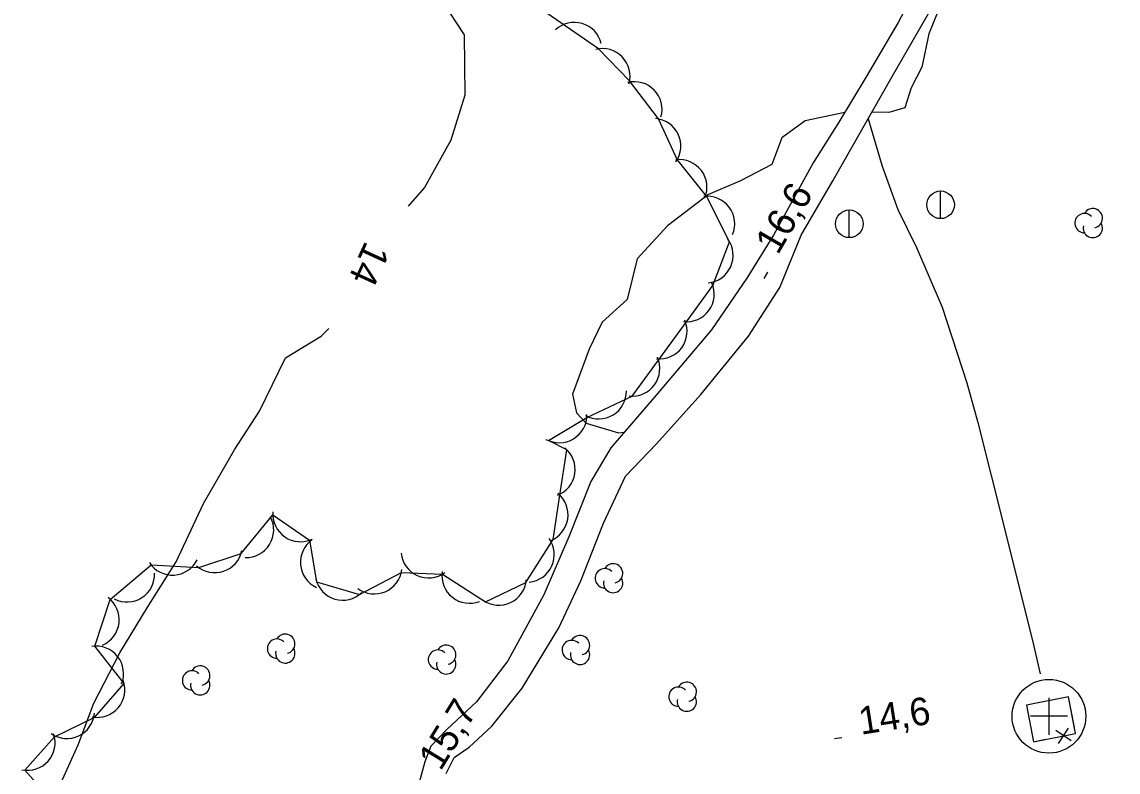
# Model space of a CAD drawing. Extents: x 643342 to 646936, y 5873857 to 5876103.
# Drawn here: x 645870.1 to 645989.1, y 5875433.1 to 5875514.5 of the extents above; entities that cross this region are included whole.
import ezdxf

# ---------------------------------------------------------------- set-up
doc = ezdxf.new("R2010")
doc.units = 0
for name, color, linetype in [('Niveau 2', 7, 'Continuous'), ('Niveau 21', 7, 'Continuous'), ('Niveau 22', 7, 'Continuous'), ('Niveau 3', 7, 'Continuous'), ('Niveau 34', 7, 'Continuous'), ('Niveau 36', 7, 'Continuous'), ('Niveau 37', 7, 'Continuous'), ('Niveau 44', 7, 'Continuous')]:
    doc.layers.add(name, color=color, linetype=linetype)

msp = doc.modelspace()

# ---------------------------------------------------------------- linework, layer by layer
at = {"layer": 'Niveau 2'}
for points in [[(645972.21, 5875521.47), (645972.26, 5875521.25), (645970.38, 5875517.91), (645968.52, 5875513.24), (645967.77, 5875509.63), (645966.59, 5875507.36), (645965.89, 5875505.2), (645964.16, 5875504.69), (645962.33, 5875504.72)], [(645912.02, 5875494.55), (645913.77, 5875496.53), (645916.66, 5875501.73), (645918.18, 5875506.6), (645918.11, 5875513.13), (645915.77, 5875516.71)], [(645959.38, 5875504.71), (645955.1, 5875503.81), (645952.55, 5875501.95), (645951.46, 5875499.07), (645948.07, 5875497.3), (645944.6, 5875495.81), (645940.16, 5875492.4), (645936.86, 5875488.81), (645935.76, 5875484.4), (645933.04, 5875481.93), (645931.66, 5875479.02), (645929.85, 5875474.12), (645930.25, 5875472.1), (645931.32, 5875470.98), (645934.84, 5875469.94), (645935.45, 5875470)], [(645874.15, 5875431.58), (645876.18, 5875436.1), (645877.87, 5875440.59), (645880.68, 5875446.08), (645883.67, 5875450.94), (645886.83, 5875455.94), (645889.78, 5875462.27), (645893.19, 5875468.17), (645895.86, 5875472.29), (645898.69, 5875478.07), (645902.55, 5875480.43), (645903.37, 5875481.26)]]:
    msp.add_lwpolyline(points, dxfattribs=at)
at = {"layer": 'Niveau 21'}
for points in [[(645916.11, 5875432.97), (645916.98, 5875434.72), (645918.62, 5875435.84), (645921.07, 5875438.1), (645924.38, 5875442.23), (645928.35, 5875448.78), (645930.73, 5875453.86), (645933.21, 5875460.14), (645935.59, 5875465.22), (645938.95, 5875468.76), (645943.76, 5875474.1), (645948.94, 5875480.42), (645952.34, 5875485.72), (645954.65, 5875491.38), (645958.1, 5875497.27), (645964.53, 5875508.6), (645969.16, 5875516.62), (645973.05, 5875522.8), (645977.54, 5875528.8), (645982.64, 5875535.69), (645984.02, 5875539.12), (645987.33, 5875558.85), (645988.91, 5875563.6), (645990.31, 5875564.69)], [(645968.09, 5875519.95), (645965.17, 5875514.46), (645961.72, 5875508.56), (645958.74, 5875503.66), (645955.94, 5875499.24), (645951.65, 5875491.38), (645948.77, 5875486.72), (645944.92, 5875481.13), (645938.9, 5875474.02), (645934.01, 5875468.32), (645931.83, 5875464.67), (645929.44, 5875458.64), (645926.73, 5875452.35), (645922.82, 5875445.21), (645919.43, 5875440.73), (645916.23, 5875437.79), (645914.44, 5875435.95), (645913.8, 5875434.23), (645911.54, 5875425.97)]]:
    msp.add_lwpolyline(points, dxfattribs=at)
at = {"layer": 'Niveau 22'}
msp.add_lwpolyline([(645961.93, 5875504.02), (645963.44, 5875498.87), (645965.14, 5875494.18), (645967.17, 5875490.06), (645969.95, 5875483.56), (645972.65, 5875475.36), (645973.83, 5875471.07), (645976.74, 5875459.56), (645979.86, 5875446.94), (645980.59, 5875443.77)], dxfattribs=at)
at = {"layer": 'Niveau 3'}
for p, q in [((645950.64, 5875486.68), (645951.05, 5875487.37)), ((645958.29, 5875436.77), (645959.08, 5875436.89))]:
    msp.add_line(p, q, dxfattribs=at)
at = {"layer": 'Niveau 34'}
for p, q in [((645981.55, 5875441.18), (645981.55, 5875437.18)), ((645983.55, 5875439.18), (645979.55, 5875439.18))]:
    msp.add_line(p, q, dxfattribs=at)
msp.add_circle((645981.55, 5875439.18), 4, dxfattribs=at)
at = {"layer": 'Niveau 36'}
for points in [[(645969.79, 5875493.18), (645969.79, 5875496.18)], [(645959.88, 5875491.12), (645959.88, 5875494.12)]]:
    msp.add_lwpolyline(points, dxfattribs=at)
for centre in [(645969.79, 5875494.68), (645959.88, 5875492.62)]:
    msp.add_circle(centre, 1.5, dxfattribs=at)
at = {"layer": 'Niveau 37'}
for points in [[(645983.66, 5875441.29), (645979.12, 5875440.39), (645979.86, 5875436.42), (645981.16, 5875436.68)], [(645983.66, 5875441.29), (645979.12, 5875440.39), (645979.86, 5875436.42), (645984.44, 5875437.32), (645983.66, 5875441.29)], [(645984.31, 5875437.97), (645983.66, 5875441.29)], [(645983.96, 5875436.51), (645982.29, 5875437.62)], [(645982.57, 5875436.23), (645983.68, 5875437.89)]]:
    msp.add_lwpolyline(points, dxfattribs=at)
at = {"layer": 'Niveau 44'}
for points in [[(645881.16, 5875442.75), (645877.98, 5875446.8), (645879.66, 5875451.87), (645884.09, 5875455.6), (645889.26, 5875455.31), (645893.87, 5875456.85), (645897.3, 5875461.04), (645901.3, 5875458.29), (645902.06, 5875453.78), (645906.71, 5875452.4), (645911.26, 5875454.8), (645915.71, 5875454.61), (645920.39, 5875451.6), (645924.78, 5875453.68), (645927.72, 5875458.36), (645928.46, 5875463.16), (645929.23, 5875468.1), (645927.24, 5875469.09), (645931.39, 5875471.61), (645936.31, 5875473.92), (645939.17, 5875477.84), (645942.21, 5875481.99), (645945.07, 5875485.91), (645946.87, 5875490.68), (645944.38, 5875495.61), (645941.21, 5875499.61), (645939.16, 5875504), (645936.03, 5875508.12), (645932.66, 5875511.61), (645927.04, 5875515.47)], [(645873.98, 5875429.32), (645870.38, 5875433.32), (645873.59, 5875436.96), (645878, 5875439.07), (645881.16, 5875442.75)]]:
    msp.add_lwpolyline(points, dxfattribs=at)
for centre, radius, start, end in [((645930.04, 5875511.48), 3, 13.5717, 133.5497), ((645930.04, 5875511.48), 3, 13.5717, 133.5497), ((645930.04, 5875511.48), 3, 13.5717, 133.5497), ((645933.08, 5875508.64), 3, 344.0038, 103.9817), ((645933.08, 5875508.64), 3, 344.0038, 103.9817), ((645933.08, 5875508.64), 3, 344.0038, 103.9817), ((645936.55, 5875505.04), 3, 344.0038, 103.9817), ((645936.55, 5875505.04), 3, 344.0038, 103.9817), ((645936.55, 5875505.04), 3, 344.0038, 103.9817), ((645938.59, 5875501.06), 3, 325.051, 85.0289), ((645938.59, 5875501.06), 3, 325.051, 85.0289), ((645938.59, 5875501.06), 3, 325.051, 85.0289), ((645941.43, 5875496.59), 3, 337.1802, 97.1582), ((645941.43, 5875496.59), 3, 337.1802, 97.1582), ((645941.43, 5875496.59), 3, 337.1802, 97.1582), ((645944.45, 5875492.61), 3, 337.1802, 97.1582), ((645944.45, 5875492.61), 3, 337.1802, 97.1582), ((645944.45, 5875492.61), 3, 337.1802, 97.1582), ((645985.41, 5875492.69), 1.05, 44.1154, 269.804), ((645986.31, 5875493.22), 1.05, 282.2692, 149.7263), ((645986.31, 5875492.17), 1.05, 166.9369, 29.6212), ((645944.27, 5875489.19), 3, 275.8808, 35.8587), ((645944.27, 5875489.19), 3, 275.8808, 35.8587), ((645944.27, 5875489.19), 3, 275.8808, 35.8587), ((645942.22, 5875484.99), 3, 263.8351, 23.813), ((645942.22, 5875484.99), 3, 263.8351, 23.813), ((645942.22, 5875484.99), 3, 263.8351, 23.813), ((645939.27, 5875480.95), 3, 263.8351, 23.813), ((645939.27, 5875480.95), 3, 263.8351, 23.813), ((645939.27, 5875480.95), 3, 263.8351, 23.813), ((645936.31, 5875476.92), 3, 263.8351, 23.813), ((645936.31, 5875476.92), 3, 263.8351, 23.813), ((645936.31, 5875476.92), 3, 263.8351, 23.813), ((645932.68, 5875474.45), 3, 241.2245, 1.2025), ((645932.68, 5875474.45), 3, 241.2245, 1.2025), ((645932.68, 5875474.45), 3, 241.2245, 1.2025), ((645928.4, 5875471.86), 3, 241.2245, 1.2025), ((645928.4, 5875471.86), 3, 241.2245, 1.2025), ((645928.4, 5875471.86), 3, 241.2245, 1.2025), ((645927.12, 5875465.97), 3, 291.1762, 51.1542), ((645927.12, 5875465.97), 3, 291.1762, 51.1542), ((645927.12, 5875465.97), 3, 291.1762, 51.1542), ((645926.35, 5875461.03), 3, 291.1762, 51.1542), ((645926.35, 5875461.03), 3, 291.1762, 51.1542), ((645926.35, 5875461.03), 3, 291.1762, 51.1542), ((645900.3, 5875461.12), 3, 175.4953, 295.4732), ((645900.3, 5875461.12), 3, 175.4953, 295.4732), ((645900.3, 5875461.12), 3, 175.4953, 295.4732), ((645894.4, 5875459.41), 3, 268.0136, 27.9915), ((645894.4, 5875459.41), 3, 268.0136, 27.9915), ((645894.4, 5875459.41), 3, 268.0136, 27.9915), ((645903.3, 5875455.89), 3, 124.9716, 244.9495), ((645903.3, 5875455.89), 3, 124.9716, 244.9495), ((645903.3, 5875455.89), 3, 124.9716, 244.9495), ((645924.85, 5875456.73), 3, 275.6381, 35.6161), ((645924.85, 5875456.73), 3, 275.6381, 35.6161), ((645924.85, 5875456.73), 3, 275.6381, 35.6161), ((645891.01, 5875457.76), 3, 228.4897, 348.4676), ((645891.01, 5875457.76), 3, 228.4897, 348.4676), ((645891.01, 5875457.76), 3, 228.4897, 348.4676), ((645914.21, 5875457.2), 3, 186.0163, 305.9943), ((645914.21, 5875457.2), 3, 186.0163, 305.9943), ((645914.21, 5875457.2), 3, 186.0163, 305.9943), ((645886.41, 5875457.5), 3, 213.3736, 333.3516), ((645886.41, 5875457.5), 3, 213.3736, 333.3516), ((645886.41, 5875457.5), 3, 213.3736, 333.3516), ((645934.24, 5875454.69), 1.05, 282.2692, 149.7263), ((645881.47, 5875454.58), 3, 242.784, 2.762), ((645881.47, 5875454.58), 3, 242.784, 2.762), ((645881.47, 5875454.58), 3, 242.784, 2.762), ((645908.33, 5875455.46), 3, 233.1933, 353.1713), ((645908.33, 5875455.46), 3, 233.1933, 353.1713), ((645908.33, 5875455.46), 3, 233.1933, 353.1713), ((645918.66, 5875454.44), 3, 171.4617, 291.4397), ((645918.66, 5875454.44), 3, 171.4617, 291.4397), ((645918.66, 5875454.44), 3, 171.4617, 291.4397), ((645933.34, 5875454.16), 1.05, 44.1154, 269.804), ((645904.89, 5875454.78), 3, 193.4879, 313.4659), ((645904.89, 5875454.78), 3, 193.4879, 313.4659), ((645904.89, 5875454.78), 3, 193.4879, 313.4659), ((645921.83, 5875454.24), 3, 235.3639, 355.3419), ((645921.83, 5875454.24), 3, 235.3639, 355.3419), ((645921.83, 5875454.24), 3, 235.3639, 355.3419), ((645934.24, 5875453.64), 1.05, 166.9369, 29.6212), ((645877.63, 5875449.66), 3, 293.4336, 53.4115), ((645877.63, 5875449.66), 3, 293.4336, 53.4115), ((645877.63, 5875449.66), 3, 293.4336, 53.4115), ((645897.76, 5875446.52), 1.05, 44.1154, 269.804), ((645898.66, 5875447.05), 1.05, 282.2692, 149.7263), ((645929.75, 5875446.37), 1.05, 44.1154, 269.804), ((645930.65, 5875446.9), 1.05, 282.2692, 149.7263), ((645878.1, 5875443.8), 3, 338.1587, 98.1366), ((645878.1, 5875443.8), 3, 338.1587, 98.1366), ((645878.1, 5875443.8), 3, 338.1587, 98.1366), ((645898.66, 5875446), 1.05, 166.9369, 29.6212), ((645915.23, 5875445.33), 1.05, 44.1154, 269.804), ((645916.13, 5875445.86), 1.05, 282.2692, 149.7263), ((645930.65, 5875445.85), 1.05, 166.9369, 29.6212), ((645916.13, 5875444.81), 1.05, 166.9369, 29.6212), ((645888.53, 5875443.07), 1.05, 44.1154, 269.804), ((645889.43, 5875443.6), 1.05, 282.2692, 149.7263), ((645878.24, 5875442.06), 3, 259.3892, 19.3672), ((645878.24, 5875442.06), 3, 259.3892, 19.3672), ((645878.24, 5875442.06), 3, 259.3892, 19.3672), ((645889.43, 5875442.55), 1.05, 166.9369, 29.6212), ((645941.34, 5875441.3), 1.05, 44.1154, 269.804), ((645942.24, 5875441.83), 1.05, 282.2692, 149.7263), ((645942.24, 5875440.78), 1.05, 166.9369, 29.6212), ((645874.94, 5875439.77), 3, 235.4729, 355.4508), ((645874.94, 5875439.77), 3, 235.4729, 355.4508), ((645874.94, 5875439.77), 3, 235.4729, 355.4508), ((645870.67, 5875436.31), 3, 258.5469, 18.5249), ((645870.67, 5875436.31), 3, 258.5469, 18.5249), ((645870.67, 5875436.31), 3, 258.5469, 18.5249)]:
    msp.add_arc(centre, radius, start, end, dxfattribs=at)

# ---------------------------------------------------------------- texts
at = {"layer": 'Niveau 2'}
msp.add_text('14', height=3, rotation=245.3603, dxfattribs=at).set_placement((645907.37, 5875490.87))
at = {"layer": 'Niveau 3'}
for s, rotation, p in [('16,6 ', 59.9121, (645952.12, 5875489.15)), ('15,7 ', 58.4653, (645915.51, 5875433.15)), ('14,6 ', 8.941, (645961.14, 5875437.17))]:
    msp.add_text(s, height=3, rotation=rotation, dxfattribs=at).set_placement(p)

doc.saveas('drawing.dxf')
